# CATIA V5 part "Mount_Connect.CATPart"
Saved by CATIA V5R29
Part number: Mount_Connect_01
Source: Unknown
Bounding box of the stored display mesh (mm): x -80 to 35, y -25 to 25, z -45 to 45
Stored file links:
  C:\가치같이\SmartFactory_BoxErectorConveyor\Boxing(under)\Mount_Connect.CATPart
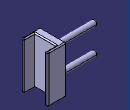
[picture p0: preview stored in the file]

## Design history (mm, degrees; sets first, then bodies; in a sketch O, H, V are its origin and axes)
Body1 (main body)
  Solid1 "PartBody": solid without history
